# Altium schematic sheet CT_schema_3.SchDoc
size 379 x 228 mm
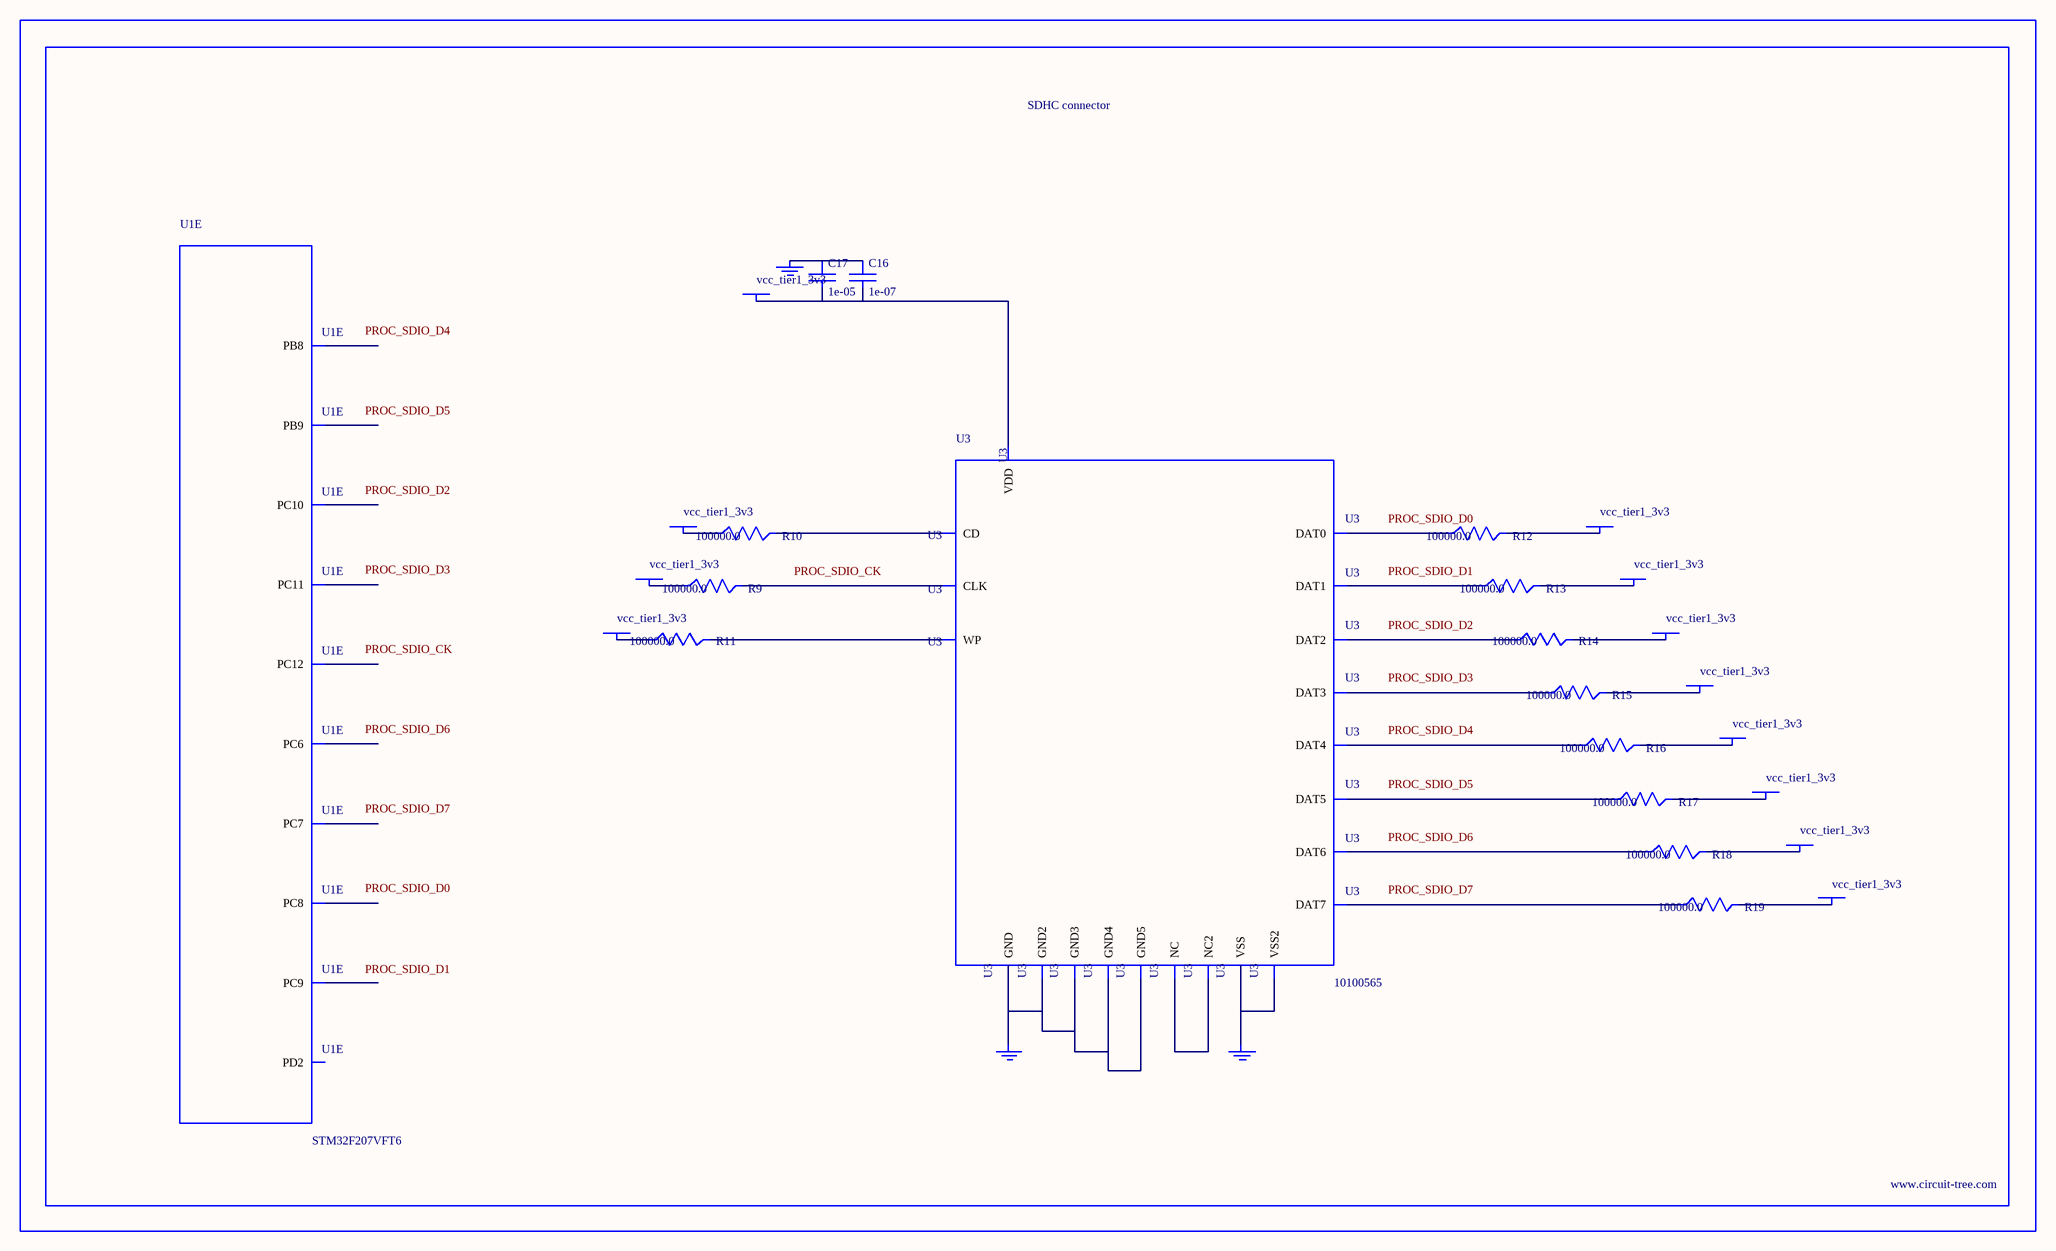
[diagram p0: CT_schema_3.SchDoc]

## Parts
BORDER2  (no value)
C16  1e-07  [C0402]
C17  1e-05  [C0805]
GND_INSTANCE_2_0  (no value)
GND_INSTANCE_2_1  (no value)
GND_INSTANCE_2_2  (no value)
POWER_INSTANCE_2_0  vcc_tier1_3v3
POWER_INSTANCE_2_1  vcc_tier1_3v3
POWER_INSTANCE_2_2  vcc_tier1_3v3
POWER_INSTANCE_2_3  vcc_tier1_3v3
POWER_INSTANCE_2_4  vcc_tier1_3v3
POWER_INSTANCE_2_5  vcc_tier1_3v3
POWER_INSTANCE_2_6  vcc_tier1_3v3
POWER_INSTANCE_2_7  vcc_tier1_3v3
POWER_INSTANCE_2_8  vcc_tier1_3v3
POWER_INSTANCE_2_9  vcc_tier1_3v3
POWER_INSTANCE_2_10  vcc_tier1_3v3
POWER_INSTANCE_2_11  vcc_tier1_3v3
R9  100000.0  [R0603]
R10  100000.0  [R0603]
R11  100000.0  [R0603]
R12  100000.0  [R0603]
R13  100000.0  [R0603]
R14  100000.0  [R0603]
R15  100000.0  [R0603]
R16  100000.0  [R0603]
R17  100000.0  [R0603]
R18  100000.0  [R0603]
R19  100000.0  [R0603]
U1  STM32F207VFT6  [LQFP100]  (part E of 7)
U3  10100565  [10100565]

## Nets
NetC16_1: C16.1 C17.1 GND_INSTANCE_2_0.0(GND)
NetC16_2: C16.2 C17.2 POWER_INSTANCE_2_7.0(PWR) U3.9(VDD)
NetGND_INSTANCE_2_1_0: GND_INSTANCE_2_1.0(GND) U3.6(VSS) U3.10(VSS2)
NetGND_INSTANCE_2_2_0: GND_INSTANCE_2_2.0(GND) U3.12(GND) U3.16(GND2) U3.17(GND3) U3.20(GND4) U3.21(GND5)
NetPOWER_INSTANCE_2_0_0: POWER_INSTANCE_2_0.0(PWR) R11.1
NetPOWER_INSTANCE_2_1_0: POWER_INSTANCE_2_1.0(PWR) R10.1
NetPOWER_INSTANCE_2_2_0: POWER_INSTANCE_2_2.0(PWR) R13.2
NetPOWER_INSTANCE_2_3_0: POWER_INSTANCE_2_3.0(PWR) R12.2
NetPOWER_INSTANCE_2_4_0: POWER_INSTANCE_2_4.0(PWR) R19.2
NetPOWER_INSTANCE_2_5_0: POWER_INSTANCE_2_5.0(PWR) R18.2
NetPOWER_INSTANCE_2_6_0: POWER_INSTANCE_2_6.0(PWR) R9.1
NetPOWER_INSTANCE_2_8_0: POWER_INSTANCE_2_8.0(PWR) R17.2
NetPOWER_INSTANCE_2_9_0: POWER_INSTANCE_2_9.0(PWR) R16.2
NetPOWER_INSTANCE_2_10_0: POWER_INSTANCE_2_10.0(PWR) R15.2
NetPOWER_INSTANCE_2_11_0: POWER_INSTANCE_2_11.0(PWR) R14.2
NetR9_2: R9.2 U3.8(CLK)
NetR10_2: R10.2 U3.2(CD)
NetR11_2: R11.2 U3.1(WP)
NetR12_1: R12.1 U3.4(DAT0)
NetR13_1: R13.1 U3.3(DAT1)
NetR14_1: R14.1 U3.15(DAT2)
NetR15_1: R15.1 U3.14(DAT3)
NetR16_1: R16.1 U3.13(DAT4)
NetR17_1: R17.1 U3.11(DAT5)
NetR18_1: R18.1 U3.7(DAT6)
NetR19_1: R19.1 U3.5(DAT7)
NetU3_18: U3.18(NC) U3.19(NC2)

Not connected (* = marked no-connect by the designer): U1 63(PC6) 64(PC7) 65(PC8) 66(PC9) 78(PC10) 79(PC11) 80(PC12) 83(PD2) 95(PB8) 96(PB9)

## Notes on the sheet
- Labels drawn without touching a wire or pin: PROC_SDIO_CK, PROC_SDIO_D0, PROC_SDIO_D1, PROC_SDIO_D2, PROC_SDIO_D3, PROC_SDIO_D4, PROC_SDIO_D5, PROC_SDIO_D6, PROC_SDIO_D7

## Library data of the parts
BORDER2 = BORDER_PAGE2
C16 = C0402C104K3RACTU
C17 = C0805C106K8RACTU
GND_INSTANCE_2_0-GND_INSTANCE_2_2 = GND
POWER_INSTANCE_2_0-POWER_INSTANCE_2_11 = PWR
R9-R19 = RC0603JR-07100KL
